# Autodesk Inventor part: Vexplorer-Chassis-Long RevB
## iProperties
Created: 2007-10
Part Number: Vexplorer-Chassis-Long RevB
Document SubType Name: Modeling
Material: Aluminum-6061-AHC
Density: 2.71 g/cm^3
